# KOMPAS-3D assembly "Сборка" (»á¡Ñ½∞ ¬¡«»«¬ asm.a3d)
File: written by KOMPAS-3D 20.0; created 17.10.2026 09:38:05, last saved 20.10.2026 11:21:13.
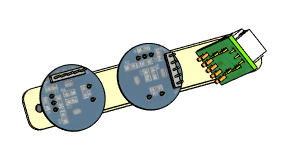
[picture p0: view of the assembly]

Document properties: Полное имя файла: D:\RicWork\Project-EPS32\box_compas\сборки компонентов\панель кнопок asm.a3d

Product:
- Part/product: Сборка
    Масса: 0.108754
  - Component [detail]: Деталь  | Масса: 0.0305378; source file: ..\корпус\панель кнопок 3bt.m3d
  - Component [assembly]: Сборка  | qty 2  | Масса: 0.0191636; source file: ..\переключатели и кнопки\TZT_EC11 asm.a3d
  - Component [assembly]: Сборка  | Масса: 0.0398888; source file: ..\переключатели и кнопки\KOQZM 2_3_4 asm.a3d

Referenced files in D:\RicWork\Project-EPS32\box_compas\переключатели и кнопки\: KOQZM 2_3_4 asm.a3d, TZT_EC11 asm.a3d
Referenced files in D:\RicWork\Project-EPS32\box_compas\корпус\: панель кнопок 3bt.m3d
